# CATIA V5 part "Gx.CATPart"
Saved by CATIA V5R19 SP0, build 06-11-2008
Part number: Gx
Publications: "L", "H", "P"
Bounding box of the stored display mesh (mm): x -20000 to 0, y 0 to 150, z 0 to 100
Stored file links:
  G:\EU_thinkMotion\CFAO_2010\MMS_groupe3\MMS_groupe3\A reprendre\evulliez\evulliez\Gx.CATPart
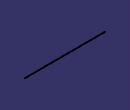
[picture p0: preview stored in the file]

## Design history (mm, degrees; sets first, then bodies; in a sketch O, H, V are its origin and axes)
Parameters
  L = 20000 mm
  H = 100 mm
  P = 150 mm
Body1 (main body)
  Sketch1 on yz-plane, origin (0, 0, 0), H (0, 1, 0), V (0, 0, 1)
    line L1 (0, 0) -> (150, 0)
    line L2 (150, 0) -> (150, 100)
    line L3 (150, 100) -> (0, 100)
    line L4 (0, 100) -> (0, 0)
    length L2 = 100 {= H}
    length L3 = 150 {= P}
    horizontal: L1 H, L3 H
    vertical: L2 V, L4 V
  Pad1: profile Sketch1, direction (-1, 0, 0), length 20000 {= L}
